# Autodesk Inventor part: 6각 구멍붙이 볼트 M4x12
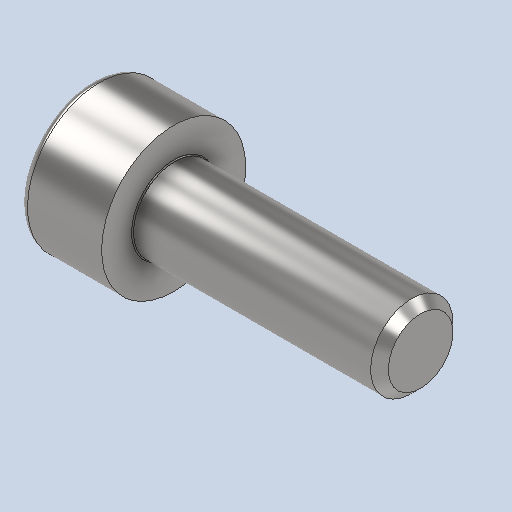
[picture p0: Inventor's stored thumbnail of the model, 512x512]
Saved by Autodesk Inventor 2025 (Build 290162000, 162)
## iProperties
Created: 2026-04
Part Number: 6각 구멍붙이 볼트 M4x12
Material: 강철, 연강
Description: 6각머리 태핑 나사
Document SubType Name: Modeling
Designer: KDI
Density: 7.85 g/cm^3
Appearance: 기본값
Author: jhkim
Sending System: Autodesk Inventor 2027
Preprocessor: ST-DEVELOPER v20.1
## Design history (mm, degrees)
feature "Solid1"
node "솔리드1"
